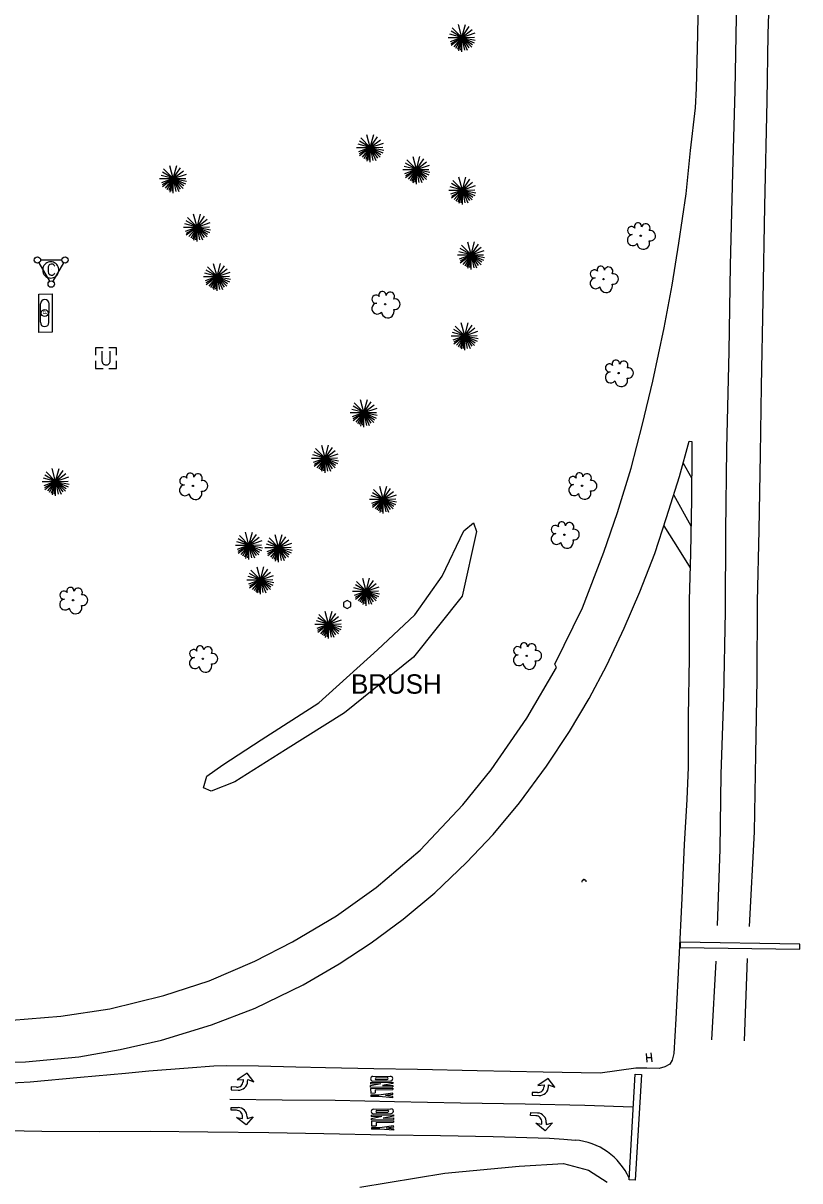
# Model space of a CAD drawing. Extents: x 2129547 to 2134906, y 657330 to 659734.
# Drawn here: x 2132201.2 to 2132482, y 657802.6 to 658221.2 of the extents above; entities that cross this region are included whole.
import ezdxf

# ---------------------------------------------------------------- set-up
doc = ezdxf.new("R2010")
doc.units = 0
for name, color, linetype in [('Default', 7, 'Continuous'), ('PM_X_Arrows', 7, 'Continuous'), ('PM_X_Cells', 7, 'Continuous'), ('PM_X_Channelizing_Line', 7, 'Continuous'), ('PM_X_Edge_Line', 7, 'Continuous'), ('PM_X_Lane_Line', 7, 'Continuous'), ('PM_X_Stop_Line', 7, 'Continuous'), ('PM_X_Transverse_Line', 7, 'Continuous'), ('RD_X_Cells', 7, 'Continuous'), ('RD_X_Concrete_Pad', 7, 'Continuous'), ('RD_X_Fence', 7, 'Continuous'), ('SN_X_Public', 7, 'Continuous'), ('UT_X_Misc_Cells', 7, 'Continuous'), ('UT_X_Tank', 7, 'Continuous'), ('UT_X_Telecom_Cells', 7, 'Continuous'), ('UT_X_Unknown_Cells', 7, 'Continuous'), ('VG_X_Cells', 7, 'Continuous'), ('VG_X_Shrub_Line_Lt', 7, 'Continuous'), ('VG_X_Text', 7, 'Continuous')]:
    doc.layers.add(name, color=color, linetype=linetype)

# ---------------------------------------------------------------- blocks, each defined once
blk = doc.blocks.new('PT500')
at = {"layer": 'Default'}
for p, q in [((-0.17, 0.079), (0.17, 0.079)), ((-0.17, -0.079), (0.17, -0.079))]:
    blk.add_line(p, q, dxfattribs=at)
blk.add_circle((0, 0), 0.0635, dxfattribs=at)
for centre, start, end in [((-0.17, 0), 90, 270), ((0.17, 0), 270, 90)]:
    blk.add_arc(centre, 0.0787, start, end, dxfattribs=at)
blk.add_text('P', height=0.0762, dxfattribs=at).set_placement((-0.018, -0.041))
blk = doc.blocks.new('DM')
at = {"layer": 'UT_X_Misc_Cells'}
blk.add_circle((0, 0), 0.00254, dxfattribs=at)
blk.add_arc((0.01016, 0), 0.01016, 90, 270, dxfattribs=at)
blk = doc.blocks.new('POST')
at = {"layer": 'RD_X_Cells'}
blk.add_lwpolyline([(-0.0165, -0.0095), (0, -0.019), (0.0165, -0.0095), (0.0165, 0.0095), (0, 0.019), (-0.0165, 0.0095), (-0.0165, -0.0095)], dxfattribs=at)
blk = doc.blocks.new('SGN1P')
at = {"layer": 'SN_X_Public'}
for p, q in [((0, 0), (-0.02032, 0)), ((0, 0.02032), (0, -0.02032))]:
    blk.add_line(p, q, dxfattribs=at)
blk = doc.blocks.new('TREE')
at = {"layer": 'VG_X_Cells'}
blk.add_circle((0, 0), 0.00305, dxfattribs=at)
for centre, radius, start, end in [((-0.0125, 0.0428), 0.0167, 354.0047, 205.9741), ((0.0232, 0.0359), 0.0197, 323.83, 165.0376), ((-0.0362, -0.0197), 0.0251, 96.1722, 320.5737), ((-0.042, 0.0237), 0.0187, 39.0625, 279.5412), ((0.0439, 0.0005), 0.0243, 259.1453, 101.4596), ((0.012, -0.0331), 0.029, 184.9476, 19.4572)]:
    blk.add_arc(centre, radius, start, end, dxfattribs=at)
blk = doc.blocks.new('POINT_DISPLAY')
at = {"layer": 'Default'}
blk.add_line((0, 0), (0, 0), dxfattribs=at)
blk = doc.blocks.new('UBOX')
at = {"layer": 'Default'}
for points in [[(-0.0051, 0.019), (-0.0191, 0.019), (-0.0191, 0.0051)], [(-0.0076, 0.0127), (-0.0076, -0.0051), (-0.0074, -0.0069), (-0.0072, -0.0075), (-0.0068, -0.0085), (-0.0064, -0.0093), (-0.0058, -0.0101), (-0.0054, -0.0105), (-0.0052, -0.0107), (-0.0044, -0.0113), (-0.0038, -0.0117), (-0.003, -0.0121), (-0.0018, -0.0125), (-0.0006, -0.0127), (0.0006, -0.0127), (0.0018, -0.0125), (0.0026, -0.0123), (0.0038, -0.0117), (0.0048, -0.0111), (0.0056, -0.0103), (0.0064, -0.0093), (0.007, -0.0081), (0.0074, -0.0071), (0.0076, -0.0051), (0.0076, 0.0127)], [(0.019, 0.0051), (0.019, 0.019), (0.0051, 0.019)], [(-0.0191, -0.0051), (-0.0191, -0.0191), (-0.0051, -0.0191)], [(0.0051, -0.0191), (0.019, -0.0191), (0.019, -0.0051)]]:
    blk.add_lwpolyline(points, dxfattribs=at)
blk.add_blockref('POINT_DISPLAY', (0, 0), dxfattribs=at)
blk = doc.blocks.new('ETREE')
at = {"layer": 'VG_X_Cells'}
for p, q in [((0, 0), (-0.0157, 0.0586)), ((0, 0), (0.016, 0.0597)), ((-0.0627, 0), (0, 0)), ((0, 0), (-0.056, 0.015)), ((0, 0), (-0.0545, -0.0198)), ((0, 0), (-0.0506, -0.029)), ((0, 0), (-0.0496, 0.0292)), ((0, 0), (-0.0496, -0.038)), ((0, 0), (-0.0443, 0.0443)), ((0, 0), (-0.0374, -0.044)), ((0, 0), (-0.0294, -0.051)), ((0, 0), (-0.0211, -0.0551)), ((0, 0), (-0.016, -0.0617)), ((0, 0), (-0.0069, -0.0583)), ((0, 0), (0.0337, 0.0493)), ((0, 0), (0.0464, 0.0356)), ((0, 0), (0.0602, 0.0204)), ((0, 0), (0.0573, 0.0012)), ((0, -0.0665), (0, 0)), ((0, 0), (0.0117, -0.0589)), ((0, 0), (0.0246, -0.0593)), ((0, 0), (0.0322, -0.0482)), ((0, 0), (0.0456, -0.0447)), ((0, 0), (0.0485, -0.0324)), ((0, 0), (0.0567, -0.0247)), ((0, 0), (0.0613, -0.0122))]:
    blk.add_line(p, q, dxfattribs=at)
blk = doc.blocks.new('PMLFT')
at = {"layer": 'PM_X_Cells'}
for points in [[(-0.57, 0), (-0.57, 0), (-0.57, 0.17), (0, 0), (-0.65, 0.76), (-1.54, 0.08), (-0.98, 0.17), (-0.98, -0.01)], [(-1.56, -0.59), (-2.03, -0.59), (-2.03, -0.85), (-1.4, -0.85)]]:
    blk.add_lwpolyline(points, dxfattribs=at)
for centre, radius, end in [((-1.56, -0.01), 0.583, 0), ((-1.4, -0.01), 0.833, 0.9085)]:
    blk.add_arc(centre, radius, 270, end, dxfattribs=at)
blk = doc.blocks.new('PMON8')
at = {"layer": 'Default'}
for p, q in [((-2.03, 0.44), (0, 0.44)), ((-2.03, 0.44), (-2.03, 0.32)), ((-2.03, 0.32), (-1.08, 0.32)), ((-2.03, 0.15), (-1.08, 0.32)), ((-2.03, 0.02), (-2.03, 0.15)), ((-2.03, 0.02), (0, 0.02)), ((-1.82, 0.99), (-0.21, 0.99)), ((-1.82, 0.57), (-0.21, 0.57)), ((-1.52, 0.87), (-0.51, 0.87)), ((-1.52, 0.7), (-0.51, 0.7)), ((0, 0.32), (-0.95, 0.15)), ((-0.95, 0.15), (0, 0.15)), ((0, 0.44), (0, 0.32)), ((0, 0.15), (0, 0.02)), ((-2.03, -0.11), (0, -0.11)), ((-2.03, -0.11), (-2.03, -0.53)), ((-2.03, -0.53), (-1.61, -0.53)), ((-1.27, -0.72), (-2.03, -0.72)), ((-2.03, -0.72), (-2.03, -0.85)), ((-1.27, -0.85), (-2.03, -0.85)), ((-1.61, -0.23), (-1.61, -0.53)), ((-1.61, -0.23), (0, -0.23)), ((0, -0.57), (-1.27, -0.72)), ((0, -0.99), (-1.27, -0.85)), ((0, -0.7), (-0.68, -0.78)), ((0, -0.87), (-0.68, -0.78)), ((0, -0.11), (0, -0.23)), ((0, -0.7), (0, -0.57)), ((0, -0.99), (0, -0.87))]:
    blk.add_line(p, q, dxfattribs=at)
for centre, radius, start, end in [((-1.82, 0.78), 0.212, 90, 270), ((-1.52, 0.78), 0.0847, 90, 270), ((-0.51, 0.78), 0.0847, 270, 90), ((-0.21, 0.78), 0.212, 270, 90)]:
    blk.add_arc(centre, radius, start, end, dxfattribs=at)
for p in [(-2.03, 0), (0, 0)]:
    blk.add_blockref('POINT_DISPLAY', p, dxfattribs=at)
blk = doc.blocks.new('PMRT')
at = {"layer": 'PM_X_Cells'}
for points in [[(-1.56, 0.59), (-2.03, 0.59), (-2.03, 0.85), (-1.4, 0.85)], [(-0.57, 0), (-0.57, 0), (-0.57, -0.17), (0, 0), (-0.65, -0.76), (-1.54, -0.08), (-0.98, -0.17), (-0.98, 0.01)]]:
    blk.add_lwpolyline(points, dxfattribs=at)
for centre, radius, start in [((-1.56, 0.01), 0.583, 360), ((-1.4, 0.01), 0.833, 359.0915)]:
    blk.add_arc(centre, radius, start, 90, dxfattribs=at)
blk = doc.blocks.new('CELLTOWER')
at = {"layer": 'Default'}
for p, q in [((-0.0229, 0.0126), (-0.0034, -0.0212)), ((0.019, 0.0177), (-0.0199, 0.0177)), ((0.022, 0.0126), (0.0025, -0.0212))]:
    blk.add_line(p, q, dxfattribs=at)
blk.add_lwpolyline([(0.006, 0.0062), (0.0052, 0.0079), (0.0044, 0.0089), (0.0036, 0.0095), (0.003, 0.0098), (0.0012, 0.0102), (-0.0006, 0.0102), (-0.0028, 0.0095), (-0.0041, 0.0086), (-0.0047, 0.0078), (-0.0054, 0.0066), (-0.0058, 0.0049), (-0.006, 0.0017), (-0.006, -0.0007), (-0.006, -0.0023), (-0.0058, -0.0038), (-0.0054, -0.0063), (-0.0052, -0.0068), (-0.0046, -0.0079), (-0.0039, -0.0087), (-0.0028, -0.0095), (-0.0018, -0.0098), (-0.0006, -0.0102), (0.0009, -0.0102), (0.0023, -0.01), (0.0028, -0.0098), (0.0034, -0.0095), (0.0041, -0.0089), (0.0049, -0.0081), (0.0055, -0.0071), (0.006, -0.0063)], dxfattribs=at)
for centre in [(-0.0259, 0.0177), (0.0249, 0.0177), (-0.0004, -0.0264)]:
    blk.add_circle(centre, 0.00594, dxfattribs=at)
blk.add_blockref('POINT_DISPLAY', (0, 0), dxfattribs=at)

msp = doc.modelspace()

# ---------------------------------------------------------------- linework, layer by layer
at = {"layer": 'PM_X_Channelizing_Line'}
msp.add_lwpolyline([(2132421.61, 657829.22), (2132404.28, 657829.77), (2132382.7, 657830.23), (2132359.33, 657830.63), (2132335.41, 657831.17), (2132314.01, 657831.56), (2132294.84, 657831.78), (2132275.9, 657831.97)], dxfattribs=at)
at = {"layer": 'PM_X_Edge_Line'}
msp.add_line((2132396.64, 657817.67), (2132400.79, 657817.32), dxfattribs=at)
for points in [[(2132197.15, 657860.65), (2132214.8, 657862.09), (2132232.53, 657864.78), (2132252.11, 657869.6), (2132268.42, 657874.94), (2132284.99, 657882.04), (2132298.62, 657889.01), (2132314.48, 657898.45), (2132328.83, 657908.66), (2132344.66, 657922.18), (2132360.14, 657938.55), (2132370.37, 657951.17), (2132383.33, 657969.91), (2132394, 657988.24), (2132393.43, 657989.38), (2132403.44, 658009.85), (2132411.09, 658029.94), (2132416.02, 658044.29), (2132420.94, 658060.29), (2132425.13, 658076.19), (2132428.86, 658091.8), (2132432.88, 658111.05), (2132435.81, 658126.43), (2132438.21, 658141.63), (2132440.85, 658159.54), (2132442.48, 658175.22), (2132444.22, 658190.57), (2132444.65, 658197.56), (2132445.07, 658217.17), (2132445.56, 658243.86)], [(2132183.17, 657845.28), (2132202.06, 657845.55), (2132221.35, 657847.36), (2132236.23, 657850.06), (2132251.24, 657853.45), (2132269.33, 657858.97), (2132285.06, 657865.02), (2132302.46, 657873.44), (2132315.43, 657881.06), (2132326.96, 657888.66), (2132338.54, 657897.25), (2132350.03, 657906.77), (2132361.44, 657917.65), (2132371.1, 657927.79), (2132380.62, 657939.29), (2132390.41, 657952.49), (2132398.73, 657965.06), (2132405.81, 657977.05), (2132412.24, 657989), (2132418.51, 658002.38), (2132424.13, 658015.59), (2132429.53, 658029.46), (2132433.82, 658042.45), (2132438.47, 658057.34), (2132441.92, 658070.03), (2132442.98, 658069.9), (2132442.95, 658065.88), (2132442.79, 658049.1), (2132442.42, 658029.39), (2132442.01, 658012.52), (2132441.91, 657991.66), (2132441.6, 657970.51), (2132441.57, 657952.14), (2132441.07, 657940.51), (2132440.21, 657924.24), (2132439.29, 657904.79), (2132438.21, 657882.65), (2132437.17, 657861.11), (2132436.44, 657848.58), (2132435.87, 657846.15), (2132434.92, 657844.74), (2132433.21, 657843.73), (2132431.15, 657843.2), (2132426.69, 657843.3), (2132422.63, 657843.34)], [(2132422.63, 657843.34), (2132409.76, 657841.47), (2132389.22, 657841.85), (2132365.32, 657842.29), (2132343.73, 657842.78), (2132327.94, 657843.12), (2132310.48, 657843.38), (2132299.77, 657843.63), (2132286.28, 657843.99), (2132274.64, 657844.13), (2132270.1, 657844.03), (2132260.84, 657843.36), (2132246.63, 657842.17), (2132238.2, 657841.35), (2132221.87, 657839.99), (2132203.73, 657838.22), (2132190.2, 657837.46)], [(2132188.78, 657820.88), (2132207.92, 657820.48), (2132228.72, 657820.42), (2132247.1, 657820.48), (2132267.92, 657820.31), (2132290.01, 657820.01), (2132309.95, 657819.64), (2132332.48, 657819.17), (2132352.06, 657818.93), (2132371.09, 657818.56), (2132391.48, 657817.97), (2132396.64, 657817.67)]]:
    msp.add_lwpolyline(points, dxfattribs=at)
msp.add_arc((2132398.76, 657793.81), 23.6, 24.2676, 85.0657, dxfattribs=at)
at = {"layer": 'PM_X_Lane_Line'}
for p, q in [((2132451.62, 657881.97), (2132450.07, 657853.52)), ((2132462.89, 657882.92), (2132461.85, 657853.17))]:
    msp.add_line(p, q, dxfattribs=at)
for points in [[(2132474.02, 658390.07), (2132473.42, 658365.27), (2132472.95, 658339.28), (2132472.3, 658310.66), (2132471.69, 658275.89), (2132471.2, 658243.55), (2132470.4, 658217.28), (2132469.98, 658193.11), (2132469.23, 658155.06), (2132468.6, 658121.03), (2132467.94, 658090.01), (2132467.68, 658065.42), (2132467.2, 658037.93), (2132466.53, 658012.04), (2132466.4, 657983.84), (2132465.94, 657956.69), (2132465.45, 657928.79), (2132463.63, 657894.51)], [(2132462, 658386.77), (2132461, 658362.01), (2132460.74, 658334.08), (2132460.05, 658302.31), (2132459.55, 658275.55), (2132459.17, 658250.08), (2132458.99, 658223.44), (2132458.44, 658196.89), (2132457.62, 658167.15), (2132456.82, 658133.76), (2132456.35, 658102.44), (2132455.51, 658067.44), (2132455.12, 658037.58), (2132454.94, 658008.45), (2132454.34, 657977.62), (2132453.42, 657949.61), (2132453.06, 657922.55), (2132452.09, 657894.93)]]:
    msp.add_lwpolyline(points, dxfattribs=at)
at = {"layer": 'PM_X_Stop_Line'}
for points in [[(2132438.68, 657886.99), (2132481.94, 657886.3), (2132481.97, 657888.19), (2132438.71, 657888.88)], [(2132420.23, 657802.92), (2132422.47, 657841.13), (2132424.7, 657841), (2132422.46, 657802.79)]]:
    msp.add_lwpolyline(points, close=True, dxfattribs=at)
at = {"layer": 'PM_X_Transverse_Line'}
for p, q in [((2132439.78, 658062.15), (2132442.86, 658056.78)), ((2132436.39, 658050.55), (2132442.61, 658039.47))]:
    msp.add_line(p, q, dxfattribs=at)
msp.add_lwpolyline([(2132432.82, 658039.42), (2132438.33, 658030.63), (2132442.29, 658024.22)], dxfattribs=at)
at = {"layer": 'RD_X_Concrete_Pad'}
for points in [[(2132211.18, 658134.92), (2132210.7, 658134.88), (2132210.23, 658134.76), (2132209.78, 658134.57), (2132209.38, 658134.3), (2132209.02, 658133.97), (2132208.73, 658133.59), (2132208.49, 658133.17), (2132208.34, 658132.71), (2132208.26, 658132.23), (2132208.26, 658131.75), (2132208.33, 658131.27), (2132208.49, 658130.81), (2132208.72, 658130.39), (2132209.02, 658130), (2132209.37, 658129.68), (2132209.78, 658129.41), (2132210.22, 658129.21), (2132210.69, 658129.09), (2132211.18, 658129.05), (2132211.66, 658129.09), (2132212.13, 658129.21), (2132212.57, 658129.41), (2132212.98, 658129.67), (2132213.34, 658130), (2132213.63, 658130.38), (2132213.87, 658130.8), (2132214.02, 658131.26), (2132214.1, 658131.74), (2132214.1, 658132.22), (2132214.03, 658132.7), (2132213.87, 658133.16), (2132213.64, 658133.59), (2132213.34, 658133.97), (2132212.99, 658134.3), (2132212.58, 658134.56), (2132212.14, 658134.76), (2132211.67, 658134.88)], [(2132211.67, 658123.34), (2132211.73, 658109.45), (2132206.9, 658109.38), (2132206.88, 658123.23)]]:
    msp.add_lwpolyline(points, close=True, dxfattribs=at)
at = {"layer": 'RD_X_Fence'}
msp.add_lwpolyline([(2132322.87, 657800.28), (2132353.63, 657805.31), (2132380.45, 657807.91), (2132396.48, 657808.77), (2132405.58, 657806.42), (2132412.34, 657802.05)], dxfattribs=at)
at = {"layer": 'VG_X_Shrub_Line_Lt'}
msp.add_lwpolyline([(2132287.24, 657962.07), (2132308.04, 657975.49), (2132329.27, 657994.56), (2132342.83, 658007.28), (2132352.7, 658021.19), (2132360.49, 658037.61), (2132364, 658040.58), (2132365.09, 658037.45), (2132359.89, 658014.06), (2132342.29, 657992.01), (2132317.39, 657971.8), (2132296.07, 657958.39), (2132277.77, 657946.91), (2132269.17, 657943.52), (2132266.39, 657944.72), (2132267.56, 657948.97), (2132273.42, 657953.03)], close=True, dxfattribs=at)

# ---------------------------------------------------------------- block references
at = {"layer": 'PM_X_Arrows'}
for name, p, xscale, yscale, rotation in [('PMLFT', (2132284.57, 657838.35), 3.9370000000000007, 3.937, -3.4265765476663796), ('PMON8', (2132334.81, 657836.48), 3.9370000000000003, 3.9370000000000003, 0.5100379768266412), ('PMLFT', (2132393.35, 657836.45), 3.9370000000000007, 3.9370000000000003, -3.0636522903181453), ('PMRT', (2132284.39, 657825.73), 3.9370000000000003, 3.9370000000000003, -0.3445406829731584), ('PMON8', (2132335.08, 657824.72), 3.9370000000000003, 3.9370000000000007, 1.2456944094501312), ('PMRT', (2132392.55, 657823.53), 3.937, 3.9370000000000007, -2.426891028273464)]:
    msp.add_blockref(name, p, dxfattribs=dict(at, xscale=xscale, yscale=yscale, rotation=rotation))
at = {"layer": 'RD_X_Cells', "xscale": 78.74000000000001, "yscale": 78.74000000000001}
msp.add_blockref('POST', (2132318.32, 658011), dxfattribs=at)
at = {"layer": 'SN_X_Public', "yscale": 78.74000000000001}
for p, xscale, rotation in [((2132426.65, 657847.03), 78.74, -174.2661584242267), ((2132428.28, 657847.22), 78.74000000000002, 6.332984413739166)]:
    msp.add_blockref('SGN1P', p, dxfattribs=dict(at, xscale=xscale, rotation=rotation))
at = {"layer": 'UT_X_Misc_Cells', "xscale": 78.74000000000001, "yscale": 78.74, "rotation": -84.67090766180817}
msp.add_blockref('DM', (2132403.9, 657911.46), dxfattribs=at)
at = {"layer": 'UT_X_Tank', "xscale": 19.684999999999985, "yscale": 19.68499999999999, "rotation": 89.50583734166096}
msp.add_blockref('PT500', (2132209.01, 658116.39), dxfattribs=at)
at = {"layer": 'UT_X_Telecom_Cells', "xscale": 196.85000000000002, "yscale": 196.85000000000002}
msp.add_blockref('CELLTOWER', (2132211.43, 658132.1), dxfattribs=at)
at = {"layer": 'UT_X_Unknown_Cells', "xscale": 196.85000000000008, "yscale": 196.85000000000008}
msp.add_blockref('UBOX', (2132231.16, 658100.14), dxfattribs=at)
at = {"layer": 'VG_X_Cells', "xscale": 78.74000000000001, "yscale": 78.74000000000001}
for name, p in [('ETREE', (2132359.83, 658216.1)), ('ETREE', (2132326.7, 658176.25)), ('ETREE', (2132255.48, 658165.03)), ('ETREE', (2132343.37, 658168.28)), ('ETREE', (2132359.97, 658160.9)), ('ETREE', (2132264.07, 658147.51)), ('TREE', (2132424.44, 658144.35)), ('ETREE', (2132363.14, 658137.42)), ('ETREE', (2132271.28, 658129.62)), ('TREE', (2132411, 658128.7)), ('TREE', (2132332.07, 658119.56)), ('ETREE', (2132360.82, 658108.2)), ('TREE', (2132416.46, 658094.69)), ('ETREE', (2132324.38, 658080.39)), ('ETREE', (2132310.35, 658063.91)), ('ETREE', (2132212.95, 658055.52)), ('TREE', (2132262.57, 658053.86)), ('TREE', (2132403.24, 658053.95)), ('ETREE', (2132331.37, 658049.11)), ('TREE', (2132396.88, 658036.24)), ('ETREE', (2132282.84, 658032.49)), ('ETREE', (2132293.56, 658031.58)), ('ETREE', (2132286.97, 658019.92)), ('ETREE', (2132325.2, 658015.8)), ('TREE', (2132219.22, 658012.53)), ('ETREE', (2132311.6, 658003.88)), ('TREE', (2132266.15, 657991.36)), ('TREE', (2132383.25, 657992.43))]:
    msp.add_blockref(name, p, dxfattribs=at)

# ---------------------------------------------------------------- texts
at = {"layer": 'VG_X_Text'}
msp.add_text('BRUSH', height=7, dxfattribs=at).set_placement((2132319.72, 657978.74))

doc.saveas('drawing.dxf')
